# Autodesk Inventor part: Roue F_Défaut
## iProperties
Shininess: 64.0
Length Units: 11269
Angle Units: 11279
Time Units: 11290
Mass Units: 11283
Length Display Precision: 3
Angle Display Precision: 2
Compacted: True
Part Number: Roue F_Défaut
Document SubType Name: Modeling
Created: 2006-01
Material: Par défaut
Designer: Fricot
Density: 0.0
Volumn: 0.0
Area: 0.0
PropertySet Name: Model Information
Control State: 0
Master: False
Checked Out: False
Author: Fricot
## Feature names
1. Base1
